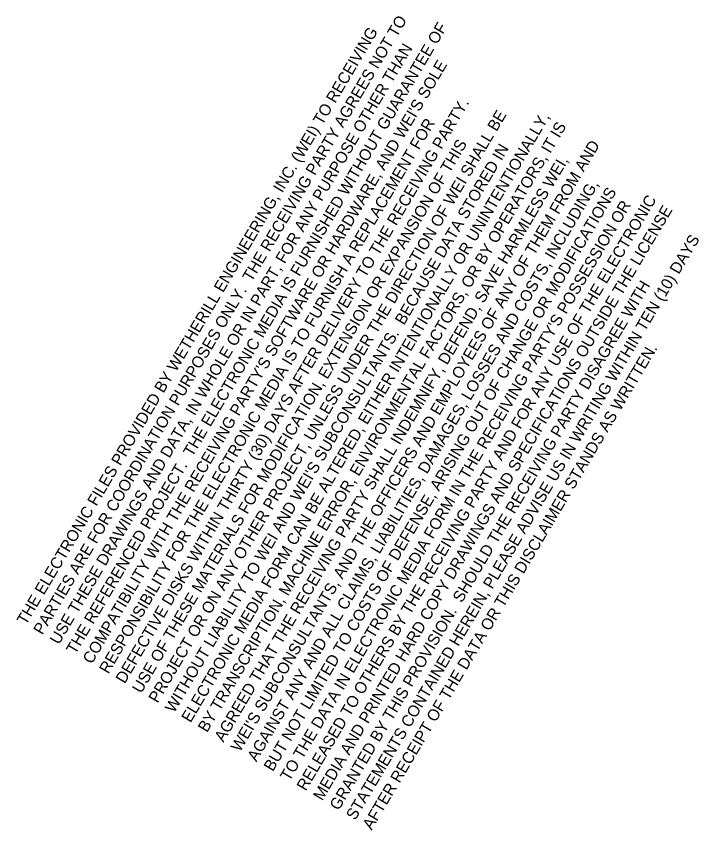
# Model space of a CAD drawing. Extents: x 2138768 to 2141436, y 406633 to 410977.
# Drawn here: x 2138768 to 2140119, y 406633 to 408245 of the extents above; entities that cross this region are included whole.
import ezdxf

# ---------------------------------------------------------------- set-up
doc = ezdxf.new("R2010")
doc.units = 0
doc.layers.add('Default', color=7, linetype='Continuous')

msp = doc.modelspace()

# ---------------------------------------------------------------- texts
at = {"layer": 'Default'}
for s, p in [('PARTIES ARE FOR COORDINATION PURPOSES ONLY.  THE RECEIVING PARTY AGREES NOT TO ', (2138819.8, 407019.4)), ('THE REFERENCED PROJECT.  THE ELECTRONIC MEDIA IS FURNISHED WITHOUT GUARANTEE OF ', (2138885, 406980.8)), ('THE ELECTRONIC FILES PROVIDED BY WETHERILL ENGINEERING, INC. (WEI) TO RECEIVING ', (2138787.2, 407038.8)), ('USE THESE DRAWINGS AND DATA, IN WHOLE OR IN PART, FOR ANY PURPOSE OTHER THAN ', (2138852.4, 407000.1)), ("COMPATIBILITY WITH THE RECEIVING PARTY'S SOFTWARE OR HARDWARE, AND WEI'S SOLE ", (2138917.6, 406961.5)), ('DEFECTIVE DISKS WITHIN THIRTY (30) DAYS AFTER DELIVERY TO THE RECEIVING PARTY.  ', (2138982.8, 406922.8)), ('PROJECT OR ON ANY OTHER PROJECT, UNLESS UNDER THE DIRECTION OF WEI SHALL BE ', (2139048, 406884.2)), ('ELECTRONIC MEDIA FORM CAN BE ALTERED, EITHER INTENTIONALLY OR UNINTENTIONALLY, ', (2139113.1, 406845.5)), ('RESPONSIBILITY FOR THE ELECTRONIC MEDIA IS TO FURNISH A REPLACEMENT FOR ', (2138950.2, 406942.2)), ('BY TRANSCRIPTION, MACHINE ERROR, ENVIRONMENTAL FACTORS, OR BY OPERATORS, IT IS ', (2139145.7, 406826.2)), ('USE OF THESE MATERIALS FOR MODIFICATION, EXTENSION OR EXPANSION OF THIS ', (2139015.4, 406903.5)), ("WEI'S SUBCONSULTANTS, AND THE OFFICERS AND EMPLOYEES OF ANY OF THEM FROM AND ", (2139210.9, 406787.6)), ("WITHOUT LIABILITY TO WEI AND WEI'S SUBCONSULTANTS.  BECAUSE DATA STORED IN ", (2139080.6, 406864.9)), ('AGREED THAT THE RECEIVING PARTY SHALL INDEMNIFY, DEFEND, SAVE HARMLESS WEI, ', (2139178.3, 406806.9)), ('AGAINST ANY AND ALL CLAIMS, LIABILITIES, DAMAGES, LOSSES AND COSTS, INCLUDING, ', (2139243.5, 406768.3)), ('BUT NOT LIMITED TO COSTS OF DEFENSE, ARISING OUT OF CHANGE OR MODIFICATIONS ', (2139276.1, 406748.9)), ('RELEASED TO OTHERS BY THE RECEIVING PARTY AND FOR ANY USE OF THE ELECTRONIC ', (2139341.3, 406710.3)), ("TO THE DATA IN ELECTRONIC MEDIA FORM IN THE RECEIVING PARTY'S POSSESSION OR ", (2139308.7, 406729.6)), ('MEDIA AND PRINTED HARD COPY DRAWINGS AND SPECIFICATIONS OUTSIDE THE LICENSE ', (2139373.9, 406691)), ('STATEMENTS CONTAINED HEREIN, PLEASE ADVISE US IN WRITING WITHIN TEN (10) DAYS ', (2139439.1, 406652.3)), ('GRANTED BY THIS PROVISION.  SHOULD THE RECEIVING PARTY DISAGREE WITH ', (2139406.5, 406671.7)), ('AFTER RECEIPT OF THE DATA OR THIS DISCLAIMER STANDS AS WRITTEN.', (2139471.7, 406633))]:
    msp.add_text(s, height=22.733, rotation=59.3391, dxfattribs=at).set_placement(p)

doc.saveas('drawing.dxf')
